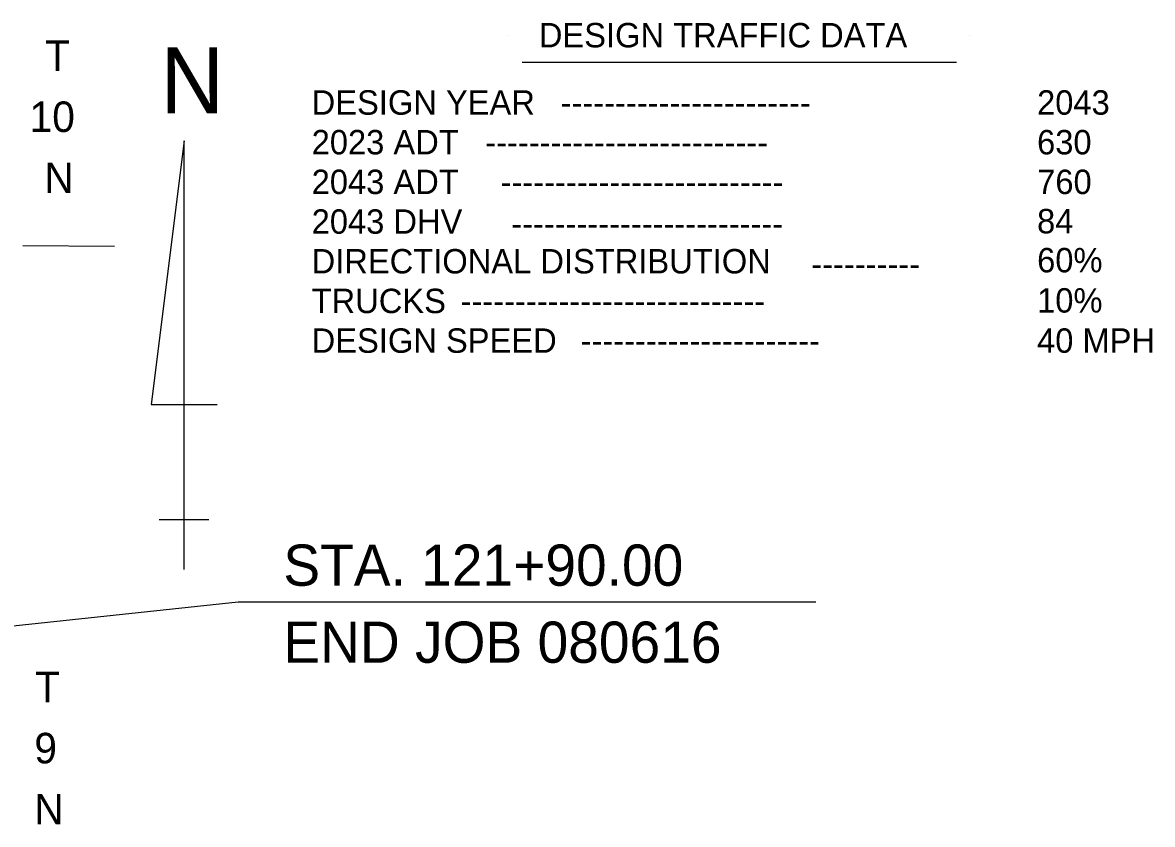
# Model space of a CAD drawing. Extents: x 1373862 to 1376999, y 1168398 to 1170455.
# Drawn here: x 1376183 to 1376923, y 1169046 to 1169571 of the extents above; entities that cross this region are included whole.
import ezdxf

# ---------------------------------------------------------------- set-up
doc = ezdxf.new("R2010")
doc.units = 0
doc.layers.add('R_Dimension', color=7, linetype='Continuous')
doc.layers.add('R_Draft', color=7, linetype='Continuous')

msp = doc.modelspace()

# ---------------------------------------------------------------- linework, layer by layer
at = {"layer": 'R_Dimension'}
msp.add_line((1376182.94, 1169425.19), (1376242.94, 1169424.78), dxfattribs=at)
at = {"layer": 'R_Draft'}
for p, q in [((1376501.09, 1169563.06), (1376501.09, 1169563.06)), ((1376803.31, 1169563.06), (1376803.31, 1169563.06)), ((1376509.98, 1169545.28), (1376794.42, 1169545.28)), ((1376288.62, 1169493.85), (1376267.02, 1169321.05)), ((1376288.62, 1169213.05), (1376288.62, 1169493.85)), ((1376267.02, 1169321.05), (1376310.22, 1169321.05)), ((1376272.32, 1169245.85), (1376304.72, 1169245.85)), ((1376323.89, 1169191.59), (1375443, 1169097.32)), ((1376702.4, 1169191.59), (1376323.89, 1169191.59))]:
    msp.add_line(p, q, dxfattribs=at)

# ---------------------------------------------------------------- texts
for s, height, p in [('DESIGN TRAFFIC DATA', 16, (1376520.91, 1169555.06)), ('T', 20, (1376197.53, 1169539.62)), ('N', 43.2, (1376273.02, 1169511.85)), ('DESIGN YEAR', 16, (1376372.1, 1169510.95)), ('2043', 16, (1376847.24, 1169510.95)), ('10', 20, (1376187.29, 1169499.62)), ('-----------------------', 16, (1376535.18, 1169510.95)), ('2023 ADT', 16, (1376372.1, 1169484.95)), ('630', 16, (1376847.24, 1169484.95)), (' --------------------------', 16, (1376479.87, 1169484.95)), ('N', 20, (1376196.97, 1169459.62)), ('2043 ADT', 16, (1376372.1, 1169458.95)), ('760', 16, (1376847.32, 1169458.95)), ('--------------------------', 16, (1376495.87, 1169458.95)), ('2043 DHV', 16, (1376372.1, 1169432.95)), ('84', 16, (1376847.23, 1169433.22)), ('-------------------------', 16, (1376502.81, 1169431.62)), ('DIRECTIONAL DISTRIBUTION', 16, (1376372.1, 1169406.95)), ('60%', 16, (1376847.28, 1169407.66)), ('----------', 16, (1376699.35, 1169405.17)), ('TRUCKS', 16, (1376372.1, 1169380.95)), ('10%', 16, (1376847.28, 1169381.3)), ('----------------------------', 16, (1376469.66, 1169380.95)), ('DESIGN SPEED', 16, (1376372.1, 1169354.96)), ('40 MPH', 16, (1376847.24, 1169354.96)), ('----------------------', 16, (1376548.28, 1169354.96)), ('STA. 121+90.00', 27, (1376353.57, 1169202.34)), ('END JOB 080616', 27, (1376353.57, 1169151.86)), ('T', 20, (1376190.92, 1169125.97)), ('9', 20, (1376190.45, 1169085.97)), ('N', 20, (1376190.36, 1169045.97))]:
    msp.add_text(s, height=height, dxfattribs=at).set_placement(p)

doc.saveas('drawing.dxf')
